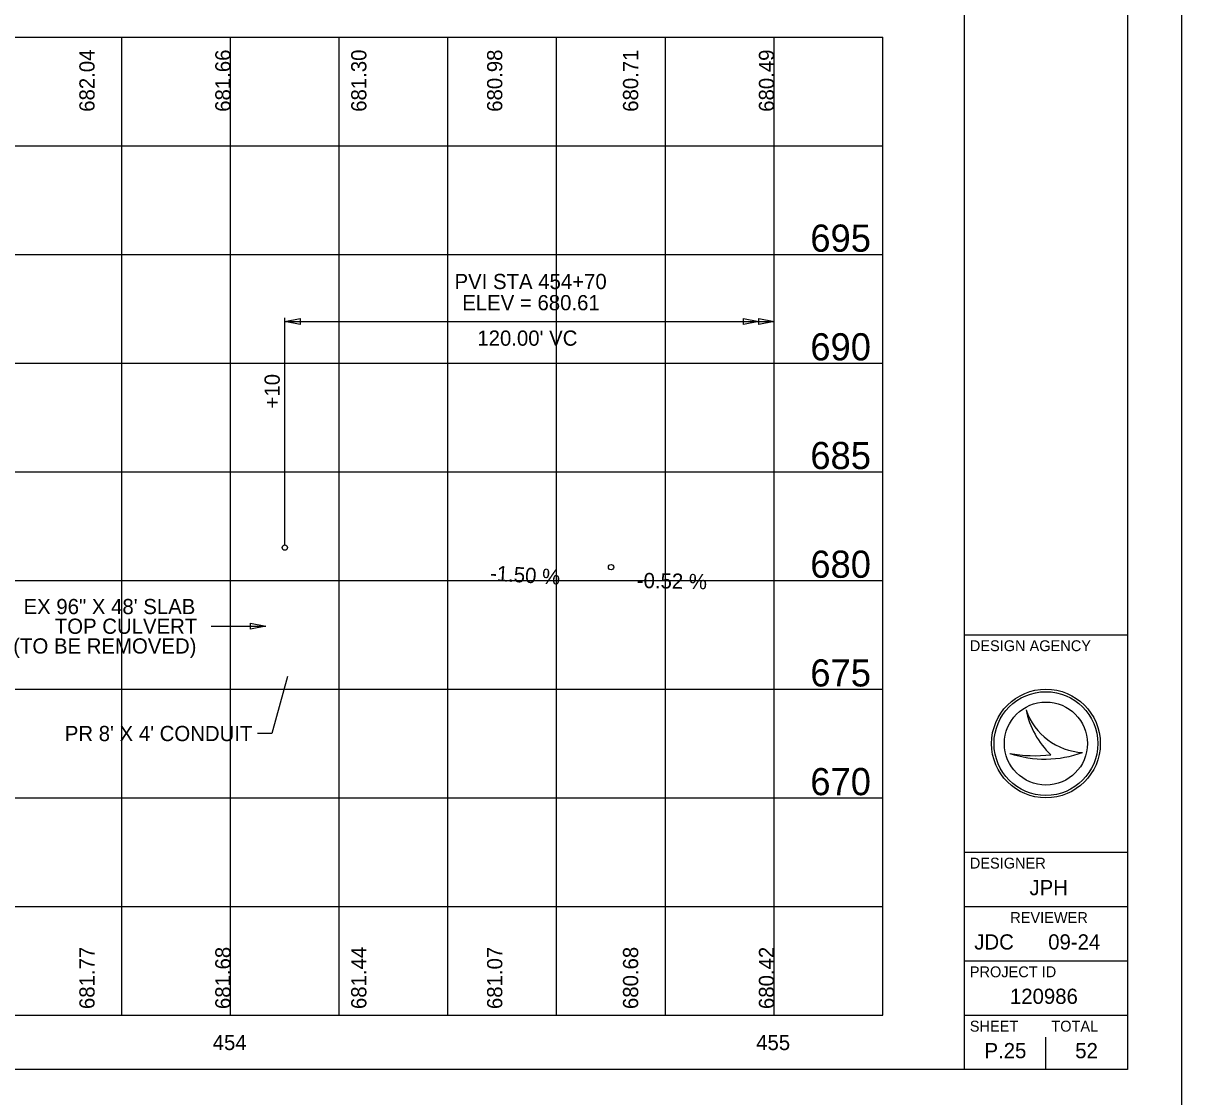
# Model space of a CAD drawing. Extents: x 0 to 3369, y -440 to 440.
# Drawn here: x 466.9 to 680, y 5 to 202.5 of the extents above; entities that cross this region are included whole.
import ezdxf

# ---------------------------------------------------------------- set-up
doc = ezdxf.new("R2010")
doc.units = 0
for name, color, linetype in [('_CIVIL_CONSTRUCTION', 7, 'Continuous'), ('DR_X_Culvert', 7, 'Continuous'), ('MT_P_PCB', 7, 'Continuous'), ('PF_X_Ground_Line', 7, 'Continuous'), ('PV_P_EOP', 7, 'Continuous'), ('SC_Scratch1', 7, 'Continuous'), ('TX_X_1', 7, 'Continuous')]:
    doc.layers.add(name, color=color, linetype=linetype)

msp = doc.modelspace()

# ---------------------------------------------------------------- linework, layer by layer
at = {"layer": '_CIVIL_CONSTRUCTION'}
for points in [[(517.8, 148.2), (517.8, 147.08), (515, 147.64)], [(599.4, 147.08), (599.4, 148.2), (602.2, 147.64)], [(602.2, 147.08), (602.2, 148.2), (605, 147.64)], [(508.7, 91.03), (508.7, 92.15), (511.5, 91.59)]]:
    msp.add_lwpolyline(points, close=True, dxfattribs=at)
at = {"layer": 'DR_X_Culvert'}
for p, q in [((45, 200), (625, 200)), ((625, 20), (625, 200)), ((651.35, 76.19), (651.35, 76.19)), ((655, 70), (655, 70)), ((661.75, 68.37), (661.75, 68.37)), ((648.34, 68.19), (648.34, 68.19)), ((45, 20), (625, 20)), ((655, 10), (655, 16)), ((647.5, 13.5), (647.5, 13.5))]:
    msp.add_line(p, q, dxfattribs=at)
for radius in [10, 9.54, 9.54, 7.64]:
    msp.add_circle((655, 70), radius, dxfattribs=at)
for centre, radius, start, end in [((662.32, 79.95), 11.6, 198.9257, 198.9319), ((666.93, 79.4), 15.91, 191.6379, 191.6421), ((662.32, 79.95), 11.6, 198.9319, 267.1657), ((666.93, 79.4), 15.91, 191.6421, 226.0947), ((654.79, 87.4), 20.26, 251.4576, 290.0832), ((652.96, 93.09), 25.32, 259.4964, 259.4995), ((654.79, 87.4), 20.26, 251.4527, 251.4576), ((652.96, 93.09), 25.32, 259.4995, 276.6672)]:
    msp.add_arc(centre, radius, start, end, dxfattribs=at)
at = {"layer": 'MT_P_PCB'}
msp.add_line((501.42, 91.59), (511.5, 91.59), dxfattribs=at)
at = {"layer": 'PF_X_Ground_Line'}
for p, q in [((640, 10), (640, 430)), ((640, 90), (670, 90)), ((640, 50), (670, 50)), ((640, 40), (670, 40)), ((640, 30), (670, 30)), ((640, 20), (670, 20))]:
    msp.add_line(p, q, dxfattribs=at)
msp.add_lwpolyline([(30, 430), (670, 430), (670, 10), (30, 10)], close=True, dxfattribs=at)
at = {"layer": 'PV_P_EOP'}
for p, q in [((515, 106.55), (515, 148.33)), ((515, 147.64), (605, 147.64)), ((515.47, 82.36), (512.62, 71.85)), ((512.62, 71.85), (509.96, 71.85))]:
    msp.add_line(p, q, dxfattribs=at)
for centre in [(515, 106.06), (575, 102.46)]:
    msp.add_circle(centre, 0.49, dxfattribs=at)
at = {"layer": 'SC_Scratch1'}
msp.add_lwpolyline([(0, 0), (680, 0), (680, 440), (0, 440)], close=True, dxfattribs=at)
at = {"layer": 'TX_X_1'}
for p, q in [((485, 20), (485, 200)), ((505, 20), (505, 200)), ((525, 20), (525, 200)), ((545, 20), (545, 200)), ((565, 20), (565, 200)), ((585, 20), (585, 200)), ((605, 20), (605, 200)), ((45, 180), (625, 180)), ((45, 160), (625, 160)), ((45, 140), (625, 140)), ((45, 120), (625, 120)), ((45, 100), (625, 100)), ((45, 80), (625, 80)), ((45, 60), (625, 60)), ((45, 40), (625, 40))]:
    msp.add_line(p, q, dxfattribs=at)

# ---------------------------------------------------------------- texts
at = {"layer": 'DR_X_Culvert'}
for s, height, p in [('695', 5, (611.66, 160.5)), ('690', 5, (611.66, 140.5)), ('685', 5, (611.66, 120.5)), ('680', 5, (611.66, 100.5)), ('DESIGN AGENCY', 2, (641, 87)), ('675', 5, (611.66, 80.5)), ('670', 5, (611.66, 60.5)), ('DESIGNER', 2, (641, 47)), ('JPH', 2.8, (651.97, 42.1)), ('REVIEWER', 2, (648.44, 37)), ('JDC', 2.8, (641.82, 32.1)), ('09-24', 2.8, (655.42, 32.1)), ('PROJECT ID', 2, (641, 27)), ('120986', 2.8, (648.38, 22.1)), ('SHEET', 2, (641, 17)), ('TOTAL', 2, (656, 17)), ('P.25', 2.8, (643.7, 12.1)), ('52', 2.8, (660.39, 12.1))]:
    msp.add_text(s, height=height, dxfattribs=at).set_placement(p)
at = {"layer": 'MT_P_PCB'}
for s, p in [('EX 96" X 48\' SLAB', (466.93, 93.81)), ('TOP CULVERT', (472.68, 90.19)), ('(TO BE REMOVED)', (465.04, 86.56))]:
    msp.add_text(s, height=2.8, dxfattribs=at).set_placement(p)
for s, p in [('681.77', (480, 21.15)), ('681.68', (505, 21.15)), ('681.44', (530, 21.15)), ('681.07', (555, 21.15)), ('680.68', (580, 21.15)), ('680.42', (605, 21.15))]:
    msp.add_text(s, height=2.8, rotation=90, dxfattribs=at).set_placement(p)
at = {"layer": 'PV_P_EOP'}
for s, rotation, p in [('682.04', 90, (480, 186.24)), ('681.66', 90, (505, 186.24)), ('681.30', 90, (530, 186.24)), ('680.98', 90, (555, 186.24)), ('680.71', 90, (580, 186.24)), ('680.49', 90, (605, 186.24)), ('+10', 90, (514.06, 131.65)), ('-1.50 %', 356.5664, (552.68, 99.99)), ('-0.52 %', 358.8051, (579.72, 98.64))]:
    msp.add_text(s, height=2.8, rotation=rotation, dxfattribs=at).set_placement(p)
for s, p in [('PVI STA 454+70', (546.21, 153.62)), ('ELEV = 680.61', (547.63, 149.72)), ("120.00' VC", (550.41, 143.2)), ("PR 8' X 4' CONDUIT", (474.52, 70.45)), ('454', (501.73, 13.6)), ('455', (601.7, 13.6))]:
    msp.add_text(s, height=2.8, dxfattribs=at).set_placement(p)

doc.saveas('drawing.dxf')
